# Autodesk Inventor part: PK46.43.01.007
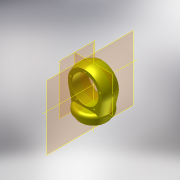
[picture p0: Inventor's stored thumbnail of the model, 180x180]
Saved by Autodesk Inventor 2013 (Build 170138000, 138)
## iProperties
Shininess: 20.0
Length Units: 11269
Angle Units: 11279
Time Units: 11290
Mass Units: 11283
Length Display Precision: 3
Angle Display Precision: 2
Created: 2001-08
Part Number: PK46.43.01.007
Material: Steel, Mild
Description: Крышка
Document SubType Name: Modeling
Designer: SOleg
Density: 7.86 g/cm^3
Density: 0.0
Volumn: 0.0
Area: 0.0
PropertySet Name: Model Information
Control State: 0
Master: False
Checked Out: True
Checked Out Date: 2008-10-09
Last Check In Date: 2008-10-09
Title: Крышка
Author: SOleg
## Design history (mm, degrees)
sketch "Эскиз13"
  geometry: L1 (38.884, -58.948)-(-23.616, -58.948); L2 (-23.616, -58.948)-(-23.616, -44.948); L3 (-23.616, -44.948)-(-24.616, -44.948); L4 (-24.616, -44.948)-(-24.616, -42.948); L5 (-24.616, -42.948)-(-37.116, -38.399); L6 (-37.116, -38.399)-(-37.116, -8.948); L7 (-37.116, -8.948)-(-49.128, 47.236); L8 (-51.116, 66.052)-(38.884, 66.052); L9 (38.884, 156.052)-(38.884, -58.948); L10 (-8.616, -58.948)-(-8.616, -31.948); L11 (-5.616, -28.948)-(38.884, -28.948); A1 r 90 centre (38.884, 66.052) between (38.884, 156.052) and (-49.128, 47.236); A2 r 3 centre (-5.616, -31.948) between (-5.616, -28.948) and (-8.616, -31.948); 1 further point
  constraints: 22 end point, 6 parallel, 5 point on circle, 5 point on line, 3 tangent, 2 centre point, 2 perpendicular, 1 coincident, 1 horizontal
  dimensions: "d142" = 90 radius of A1; "d143" = 30 distance between parallel lines of L11 L1; "d144" = 76 distance between parallel lines of L9 L6; "d145" = 47.5 distance of point (-8.616, -28.948) L11.end; "d146" = 62.5 distance between parallel lines of L9 L2; "d147" = 63.5 distance between parallel lines of L9 L4; "d148" = 20 deg angle of L3 L5; "d149" = 16 vertical distance of L1.end L4.end; "d150" = 14 distance of L1.end L2.end; "d151" = 3 radius of A2; "d163" = 125 distance from line of L1 L8.end; "d164" = 75 vertical distance of L6.end L8.end
revolve "Вращение6" sketch "Эскиз13" stored, may be unused: angle "d152" = 90 deg
node "РабОсь6"
sketch "Эскиз14"
  geometry: L1 (101.384, -58.948)-(-23.616, -58.948) reference; L2 (114.884, -38.399)-(-37.116, -38.399) reference; L3 (114.884, -38.399)-(114.884, -8.948) reference; L4 (-37.116, -38.399)-(-37.116, -8.948) reference; L5 (38.884, -101.948)-(38.884, 199.052) reference; L6 (78.884, 151.052)-(148.884, 151.052); L7 (148.884, 151.052)-(148.884, -8.948); L8 (148.884, -8.948)-(78.884, -8.948); L9 (78.884, -8.948)-(78.884, 151.052); L10 (-71.116, 151.052)-(-1.116, 151.052); L11 (-1.116, 151.052)-(-1.116, -8.948); L12 (-1.116, -8.948)-(-71.116, -8.948); L13 (-71.116, -8.948)-(-71.116, 151.052)
  constraints: 16 end point, 4 parallel, 2 horizontal, 2 perpendicular
  dimensions: "d153" = 160 distance of L6.end L7.end; "d154" = 160 distance of L12.end L10.start; "d155" = 0 distance from line of L8 L3.end; "d156" = 0 distance from line of L12 L4.end; "d157" = 40 distance between parallel lines of L5 L9; "d158" = 40 distance between parallel lines of L11 L5; "d159" = 70 distance of L6.start L6.end; "d160" = 70 distance of L10.start L10.end
extrude "Выдавливание3" cut sketch "Эскиз14" stored distance "d161" = 50; taper "d162" = 0 deg
node "РабПлоскость6"
sketch "Эскиз15"
  geometry: L1 (62.5, -35.275)-(-62.5, -35.275) reference; L2 (0, -78.275)-(0, 222.725) reference; 1 further point
  dimensions: "d165" = 0 distance from line of L2 point (0, 8.725); "d166" = 44 distance from line of L1 point (0, 8.725)
hole "Отверстие3" sketch "Эскиз15" diameter "d167" = 20; stored, may be unused: countersink angle "d171" = 82 deg, drill point angle "d173" = 118 deg; dims "d168" = 6, "d169" = 33, "d170" = 5, "d172" = 45
sketch "Эскиз16"
  geometry: C1 r 16.5 at (0, 0) reference; C2 r 10 at (0, 0) reference; C3 r 16.5 at (0, 0)
  constraints: 1 centre point, 1 coincident, 1 concentric
extrude "Выдавливание4" cut sketch "Эскиз16" stored distance "d174" = 50; taper "d175" = 0 deg
sketch "Эскиз17"
  geometry: C1 r 44.5 at (0, 0) reference; C2 r 10 at (31, 0)
  constraints: 1 centre point
  dimensions: "d176" = 0 vertical distance of C1.centre C2.centre; "d177" = 31 distance of C1.centre C2.centre; "d180" = 20 diameter of C2
extrude "Выдавливание5" cut sketch "Эскиз17" distance "d178" = 24; taper "d179" = 0 deg
sketch "Эскиз18"
  geometry: C1 r 62.5 at (0, 0); A1 r 80.623 centre (0, 0) between (78.396, -18.815) and (-78.396, -18.815) reference
  constraints: 1 centre point, 1 coincident
  dimensions: "d181" = 125 diameter of C1
extrude "Выдавливание6" cut sketch "Эскиз18" stored distance "d182" = 34; taper "d183" = 0 deg
sketch "Эскиз19" dims "d184" = 145
  geometry: L1 (0, -168)-(0, 133) reference; C1 r 5 at (0, 72.5); A1 r 80.623 centre (0, 0) between (78.396, -18.815) and (-78.396, -18.815) reference; 1 further point
  constraints: 1 centre point, 1 coincident, 1 point on line, 1 vertical alignment, 2 other
  dimensions: "d185" = 10 diameter of C1
extrude "Выдавливание7" cut sketch "Эскиз19" distance "d186" = 16; taper "d187" = 0 deg
chamfer "Фаска2" distance "d188" = 2; stored, may be unused: second distance "d189" = 2, angle "d196" = 45 deg
chamfer "Фаска3" distance "d190" = 2; stored, may be unused: second distance "d191" = 2, angle "d197" = 45 deg
node "РабОсь7"
pattern_circular "Круговой массив1" dims angle "d194" = 360 deg
node "РабПлоскость7"
mirror "ЗеркОтобр3"
fillet "Сопряжение4" dims "d198" = 15
body "Solid1"
other parameters: "d3" = 125 (derived), "d5" = 0 (derived), "d7" = 2 (derived), "d9" = 2 (derived), "d11" = 13 (derived), "d13" = 16 (derived), "d17" = 82.5 (derived), "d19" = 92.5 (derived), "d23" = 5 (derived), "d25" = 52.5 (derived), "d27" = 12.5 (derived), "d29" = 21.5 (derived), "d31" = 46 (derived), "d36" = 52.5 (derived), "d38" = 52.5 (derived), "d42" = 55 (derived), "d48" = 34 (derived), "d50" = 55 (derived), "d52" = 0 (derived), "d56" = 12.5 (derived), "d58" = 59 (derived), "d60" = 60 deg (derived), "d62" = 0 (derived), "d65" = 5 (derived), "d67" = 5 (derived), "d69" = 2 (derived), "d71" = 2 (derived), "d73" = 57.5 (derived), "d77" = 0 (derived)
